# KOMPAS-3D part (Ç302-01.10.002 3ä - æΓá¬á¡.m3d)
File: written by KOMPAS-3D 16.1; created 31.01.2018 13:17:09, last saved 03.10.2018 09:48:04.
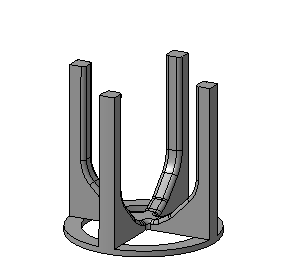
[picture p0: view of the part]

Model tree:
1. Эскиз:1
2. Операция вращения:1
     Угол 1 = 360
3. Эскиз:4
4. Операция выдавливания:3
     Расстояние 1 = 3.5; Расстояние 2 = 160
5. Эскиз:3
6. Вырезать элемент выдавливания:1
     Расстояние 1 = 78
7. Массив по концентрической сетке:2  (with: Вырезать элемент выдавливания:1, Эскиз:3)  (4 pattern instances)
     Геометрический массив = 3; Шаг 2 = 360
8. Эскиз:5
9. Вырезать элемент выдавливания:2
     Расстояние 1 = 2
10. Фаска:1
     Угол = 45; Длина 1 = 1; Длина 2 = 1
11. Скругление:1
     Радиус = 15
12. Эскиз:8
13. Операция выдавливания:4
     Расстояние 1 = 10; Расстояние 2 = 5
14. Скругление:3
     Радиус = 4
15. Скругление:5
     Радиус = 2
16. Скругление:6
     Радиус = 2
17. Эскиз:9
18. Операция выдавливания:5
     Расстояние 1 = 3
19. Эскиз:7
20. Сечение поверхностью:1  (labels: А302-01.10.002 3Д)

Expressions: v184+10
Referenced files in D:\МЭ200\Макеты\: Заготовка стакан.m3d
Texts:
  Линейный размер с обрывом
